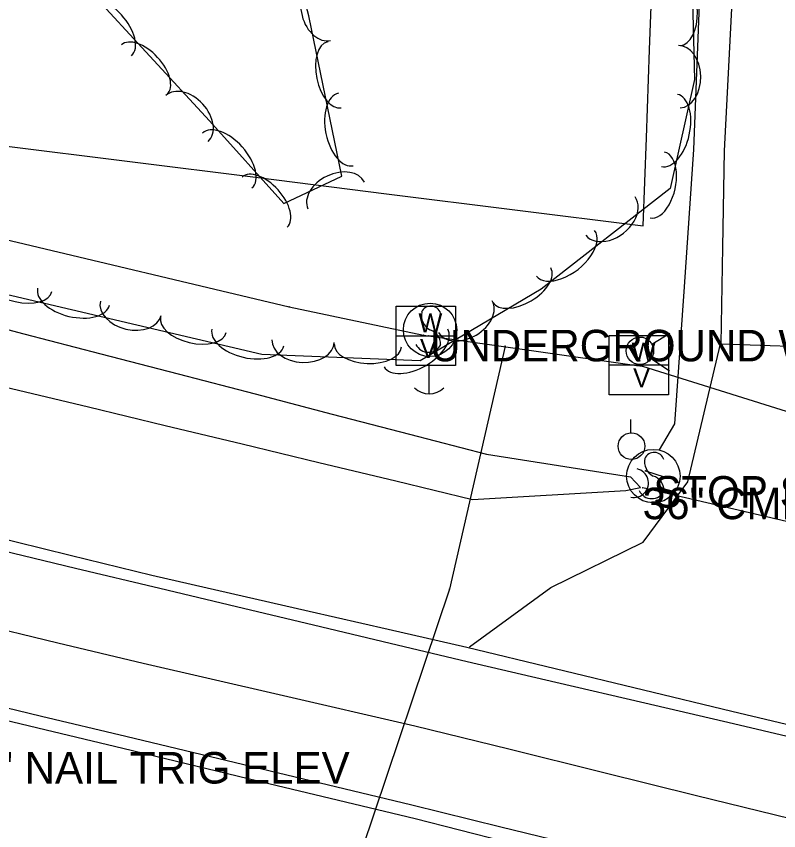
# Model space of a CAD drawing. Extents: x 1441650 to 1491889, y 345904 to 358319.
# Drawn here: x 1450968 to 1451089.1, y 353269.1 to 353398.4 of the extents above; entities that cross this region are included whole.
import ezdxf

# ---------------------------------------------------------------- set-up
doc = ezdxf.new("R2010")
doc.units = 0
for name, color, linetype in [('S_CROSS_DRAIN', 7, 'Continuous'), ('S_CROSS_DRAIN_ANNOT', 7, 'Continuous'), ('S_DITCHLINE', 7, 'Continuous'), ('S_DRG_PT_SYM', 7, 'Continuous'), ('S_EDGE_PAVEMENT', 7, 'Continuous'), ('S_GRAVEL_ROAD', 7, 'Continuous'), ('S_MSC_PT_SYM', 7, 'Continuous'), ('S_PAVEMENT_CROWN', 7, 'Continuous'), ('S_SECONDARY_CTL_ANNOT', 7, 'Continuous'), ('S_SHOULDER', 7, 'Continuous'), ('S_SIGN', 7, 'Continuous'), ('S_SIGN_ANNOT', 7, 'Continuous'), ('S_TREE', 7, 'Continuous'), ('S_UTILITY_POLE', 7, 'Continuous'), ('S_UTL_PT_SYM', 7, 'Continuous'), ('S_WATER_UTILITIES', 7, 'Continuous')]:
    doc.layers.add(name, color=color, linetype=linetype)

msp = doc.modelspace()

# ---------------------------------------------------------------- linework, layer by layer
at = {"layer": 'S_CROSS_DRAIN'}
msp.add_line((1451114.27, 353312.59), (1451067.5, 353323.6), dxfattribs=at)
msp.add_arc((1451066.12, 353324.34), 2.3, 257.1469, 77.4761, dxfattribs=at)
at = {"layer": 'S_DITCHLINE'}
for points in [[(1451081.51, 353583.7), (1451081.24, 353570.14), (1451080.98, 353556.59), (1451080.71, 353543.03), (1451080.44, 353529.48), (1451080.17, 353515.92), (1451079.9, 353502.36), (1451079.63, 353488.81), (1451079.36, 353475.25), (1451078.42, 353450.76), (1451077.48, 353426.27), (1451076.53, 353401.77), (1451075.59, 353377.28), (1451074.08, 353355.51), (1451072.56, 353333.74), (1451070.11, 353329.6)], [(1450831.65, 353381.19), (1450844.51, 353378.15), (1450857.04, 353375.18), (1450869.56, 353372.22), (1450882.09, 353369.25), (1450894.61, 353366.28), (1450907.13, 353363.32), (1450919.66, 353360.35), (1450932.18, 353357.39), (1450944.71, 353354.42), (1450956.95, 353351.23), (1450969.2, 353348.05), (1450981.44, 353344.86), (1450993.69, 353341.67), (1451005.94, 353338.48), (1451018.18, 353335.29), (1451030.43, 353332.11), (1451042.68, 353328.92), (1451065.54, 353325.34), (1451067.13, 353323.63)], [(1450829.49, 353373.88), (1450842.26, 353370.68), (1450854.83, 353367.5), (1450867.4, 353364.32), (1450879.97, 353361.13), (1450892.54, 353357.95), (1450905.12, 353354.77), (1450917.69, 353351.59), (1450930.26, 353348.41), (1450942.83, 353345.23), (1450955.04, 353342.29), (1450967.25, 353339.35), (1450979.45, 353336.42), (1450991.66, 353333.48), (1451003.87, 353330.54), (1451016.07, 353327.6), (1451028.28, 353324.67), (1451040.49, 353321.73), (1451064.83, 353323.16), (1451067.13, 353323.63)]]:
    msp.add_lwpolyline(points, dxfattribs=at)
at = {"layer": 'S_DRG_PT_SYM'}
msp.add_lwpolyline([(1451067.5, 353323.6), (1451067.5, 353323.65), (1451067.5, 353323.6), (1451067.45, 353323.6), (1451067.5, 353323.6), (1451067.5, 353323.55), (1451067.5, 353323.6), (1451067.55, 353323.6)], dxfattribs=at)
at = {"layer": 'S_EDGE_PAVEMENT'}
for points in [[(1450823.58, 353347.74), (1450835.74, 353344.83), (1450849.25, 353341.57), (1450862.76, 353338.32), (1450876.27, 353335.07), (1450889.78, 353331.81), (1450913.52, 353326.12), (1450937.25, 353320.43), (1450950.63, 353317.23), (1450964.01, 353314.03), (1450977.39, 353310.83), (1450990.77, 353307.63), (1451002.98, 353304.72), (1451015.18, 353301.82), (1451027.39, 353298.91), (1451039.6, 353296), (1451053.71, 353292.72), (1451067.83, 353289.43), (1451081.94, 353286.14), (1451096.06, 353282.85)], [(1451039.97, 353298.34), (1451052.91, 353307.73), (1451067.57, 353314.96), (1451074.68, 353324.55), (1451079.88, 353346.43), (1451092.44, 353346.01), (1451103.35, 353346.12), (1451106.46, 353341.59), (1451110.6, 353338.54), (1451119.58, 353334.06), (1451137.25, 353329.84), (1451154.93, 353325.61), (1451175.32, 353321.2), (1451195.71, 353316.78), (1451216.11, 353312.37), (1451236.5, 353307.96), (1451244, 353311.27), (1451247.51, 353313.37), (1451252.22, 353316.81), (1451258.38, 353327.82)], [(1450830.73, 353321.2), (1450843.9, 353318.04), (1450857.06, 353314.89), (1450870.22, 353311.74), (1450883.39, 353308.58), (1450907.63, 353302.76), (1450931.87, 353296.93), (1450945.25, 353293.73), (1450958.63, 353290.53), (1450972.01, 353287.34), (1450985.39, 353284.14), (1451008.11, 353278.7), (1451030.84, 353273.25), (1451044.97, 353269.78), (1451059.1, 353266.32), (1451073.24, 353262.85), (1451087.37, 353259.38), (1451099.74, 353256.51)]]:
    msp.add_lwpolyline(points, dxfattribs=at)
at = {"layer": 'S_GRAVEL_ROAD'}
msp.add_lwpolyline([(1451086.83, 353584.48), (1451086.85, 353571.29), (1451086.87, 353558.1), (1451086.9, 353544.9), (1451086.92, 353531.71), (1451086.46, 353517.63), (1451086, 353503.54), (1451085.54, 353489.45), (1451085.08, 353475.37), (1451084.52, 353462.63), (1451083.95, 353449.89), (1451083.39, 353437.15), (1451082.83, 353424.41), (1451081.65, 353400.75), (1451080.47, 353377.08), (1451080.19, 353361.77), (1451079.9, 353346.46)], dxfattribs=at)
at = {"layer": 'S_MSC_PT_SYM'}
for points in [[(1451067.93, 353326.26), (1451067.93, 353326.31), (1451067.93, 353326.26), (1451067.88, 353326.26), (1451067.93, 353326.26), (1451067.93, 353326.21), (1451067.93, 353326.26), (1451067.98, 353326.26)], [(1451070.92, 353325.33), (1451070.92, 353325.38), (1451070.92, 353325.33), (1451070.87, 353325.33), (1451070.92, 353325.33), (1451070.92, 353325.28), (1451070.92, 353325.33), (1451070.97, 353325.33)]]:
    msp.add_lwpolyline(points, dxfattribs=at)
at = {"layer": 'S_PAVEMENT_CROWN'}
msp.add_lwpolyline([(1450834.01, 353333.12), (1450847.14, 353329.9), (1450860.27, 353326.69), (1450873.4, 353323.47), (1450886.53, 353320.26), (1450910.25, 353314.51), (1450933.97, 353308.76), (1450947.51, 353305.5), (1450961.05, 353302.25), (1450974.59, 353298.99), (1450988.13, 353295.73), (1451009.73, 353290.77), (1451031.32, 353285.8), (1451046.23, 353282.12), (1451061.14, 353278.43), (1451076.05, 353274.74), (1451090.96, 353271.06)], dxfattribs=at)
at = {"layer": 'S_SHOULDER'}
for points in [[(1450824.18, 353349.95), (1450836.42, 353347.01), (1450849.81, 353343.71), (1450863.21, 353340.42), (1450876.6, 353337.12), (1450889.99, 353333.83), (1450913.88, 353328.09), (1450937.76, 353322.35), (1450950.7, 353319.2), (1450963.64, 353316.04), (1450976.57, 353312.89), (1450989.51, 353309.73), (1451002.02, 353306.87), (1451014.53, 353304.01), (1451027.04, 353301.15), (1451039.54, 353298.29), (1451053.58, 353294.91), (1451067.62, 353291.53), (1451081.66, 353288.14), (1451095.7, 353284.76)], [(1450830.29, 353319.65), (1450843.46, 353316.48), (1450856.63, 353313.3), (1450869.8, 353310.12), (1450882.97, 353306.94), (1450906.96, 353301.05), (1450930.95, 353295.16), (1450944.44, 353291.93), (1450957.93, 353288.7), (1450971.42, 353285.47), (1450984.91, 353282.23), (1451008.12, 353276.65), (1451031.33, 353271.07), (1451045.44, 353267.46), (1451059.55, 353263.84), (1451073.66, 353260.23), (1451087.76, 353256.62), (1451100.07, 353253.77)]]:
    msp.add_lwpolyline(points, dxfattribs=at)
at = {"layer": 'S_SIGN'}
msp.add_line((1451067.93, 353326.26), (1451070.92, 353325.33), dxfattribs=at)
for centre in [(1451033.72, 353348.66), (1451069.19, 353325.44)]:
    msp.add_circle(centre, 4.24, dxfattribs=at)
for centre, radius, start, end in [((1451034.89, 353350.92), 2.55, 167.1196, 241.9813), ((1451033.85, 353350.82), 1.62, 16.5258, 156.8957), ((1451033.02, 353346.38), 2.38, 358.6529, 73.7063), ((1451033.46, 353347.26), 2.17, 204.641, 335.359), ((1451070.35, 353327.69), 2.55, 167.1196, 241.9813), ((1451069.31, 353327.59), 1.62, 16.5258, 156.8957), ((1451068.49, 353323.16), 2.38, 358.6529, 73.7063), ((1451068.93, 353324.04), 2.17, 204.641, 335.359)]:
    msp.add_arc(centre, radius, start, end, dxfattribs=at)
at = {"layer": 'S_TREE'}
for points in [[(1450852.24, 353575.78), (1450857.17, 353552.77), (1450854.21, 353539.37), (1450848, 353528.9), (1450859.46, 353504.57), (1450890.34, 353466.47), (1450946.32, 353424.11), (1450979.75, 353402.41), (1450998.69, 353381.83), (1451010.51, 353368.7), (1451019.71, 353373.05), (1451014.45, 353398.5), (1451008.5, 353420.89), (1451025.86, 353434.13), (1451027.45, 353449.75), (1451001.4, 353446.33), (1450968.72, 353445.3), (1450934.63, 353475.8), (1450909.36, 353496.02), (1450896.01, 353516.09), (1450886.84, 353540.85), (1450882.03, 353567.8), (1450882.28, 353576.49)], [(1451081.45, 353507.22), (1451078.58, 353476.15), (1451074.5, 353436.69), (1451075.71, 353388.42), (1451071.87, 353371.08), (1451051.37, 353355.1), (1451032.15, 353343.74), (1451006.98, 353344.75), (1450902.46, 353369.26), (1450848.54, 353385.74), (1450833.65, 353392.55), (1450817.21, 353399.62), (1450798.23, 353391.97), (1450779.89, 353395.02), (1450763.79, 353414.42), (1450740.79, 353417.51), (1450719.03, 353412.74), (1450708.9, 353435.04), (1450659.3, 353448.63), (1450646.87, 353441.13), (1450629.34, 353447.78), (1450610.54, 353464.78)], [(1450822.89, 353395.73), (1450843.28, 353393.19), (1450863.67, 353390.64), (1450884.06, 353388.09), (1450904.46, 353385.55), (1450924.85, 353383), (1450945.24, 353380.46), (1450965.64, 353377.91), (1450986.03, 353375.37), (1451006.42, 353372.82), (1451026.81, 353370.27), (1451047.21, 353367.73), (1451067.6, 353365.18), (1451068.1, 353379.13), (1451068.6, 353393.09), (1451069.09, 353407.04)], [(1450822.89, 353395.73), (1450843.28, 353393.19), (1450863.67, 353390.64), (1450884.06, 353388.09), (1450904.46, 353385.55), (1450924.85, 353383), (1450945.24, 353380.46), (1450965.64, 353377.91), (1450986.03, 353375.37), (1451006.42, 353372.82), (1451026.81, 353370.27), (1451047.21, 353367.73), (1451067.6, 353365.18), (1451068.1, 353379.13), (1451068.6, 353393.09), (1451069.09, 353407.04)]]:
    msp.add_lwpolyline(points, dxfattribs=at)
for centre, major_axis, ratio, start_param, end_param in [((1451073.32, 353399.15), (-0.13, 5.34), 0.540699, 3.141593, 6.283185), ((1451016.66, 353399.41), (1.27, -4.79), 0.684317, 3.140814, 6.282406), ((1450982.32, 353396.49), (-3.97, 4.32), 0.54902, 3.141593, 6.283185), ((1450988.32, 353389.97), (-3.62, 3.93), 0.539658, 3.141593, 6.283185), ((1451018.54, 353389.15), (1.08, -5.24), 0.539932, 3.141593, 6.283185), ((1451073.32, 353388.85), (-0.12, 4.95), 0.68531, 3.141593, 6.283185), ((1450995.11, 353382.21), (-3.36, 3.65), 0.68399, 3.141593, 6.283185), ((1451020.34, 353380.46), (1.19, -5.75), 0.549299, 3.141593, 6.283185), ((1451071.75, 353380.32), (1.27, 5.73), 0.550084, 3.141602, 6.283194), ((1451001.5, 353375.54), (-3.93, 4.36), 0.54902, 3.141593, 6.283185), ((1451069.83, 353371.66), (1.16, 5.22), 0.540704, 3.141601, 6.283194), ((1451007.43, 353368.95), (-3.58, 3.97), 0.539658, 3.141593, 6.283185), ((1451018.81, 353369.99), (-4.48, -2.12), 0.685194, 3.141593, 6.283185), ((1451062.38, 353366.71), (3.91, 3.04), 0.685511, 3.141741, 6.283334), ((1451055.24, 353360.81), (4.63, 3.61), 0.550241, 3.141683, 6.283276), ((1451048.31, 353355.76), (4.6, 2.72), 0.540693, 3.141593, 6.283185), ((1450968.45, 353355.96), (5.21, -1.22), 0.540694, 3.141593, 6.283185), ((1450977.09, 353353.94), (5.71, -1.34), 0.550074, 3.141593, 6.283185), ((1450986.16, 353352.08), (4.82, -1.13), 0.685304, 3.141593, 6.283185), ((1451039.31, 353350.74), (4.27, 2.52), 0.685303, 3.141593, 6.283185), ((1450996.13, 353349.47), (5.21, -1.22), 0.540694, 3.141593, 6.283185), ((1451004.77, 353347.45), (5.71, -1.34), 0.550074, 3.141593, 6.283185), ((1451031.47, 353345.8), (5.05, 2.99), 0.550073, 3.141593, 6.283185), ((1451013.56, 353346.87), (4.95, -0.2), 0.685303, 3.141593, 6.283185), ((1451023.84, 353346.2), (5.34, -0.22), 0.540693, 3.141593, 6.283185)]:
    msp.add_ellipse(centre, major_axis=major_axis, ratio=ratio, start_param=start_param, end_param=end_param, dxfattribs=at)
at = {"layer": 'S_UTILITY_POLE'}
for p, q in [((1451033.51, 353343.22), (1451033.51, 353338.49)), ((1451065.6, 353332.33), (1451065.6, 353334.44))]:
    msp.add_line(p, q, dxfattribs=at)
msp.add_circle((1451065.72, 353330.19), 2.13, dxfattribs=at)
msp.add_arc((1451033.58, 353341.92), 3.41, 226.3972, 313.6028, dxfattribs=at)
at = {"layer": 'S_UTL_PT_SYM'}
for points in [[(1451011.33, 353352.33), (1451011.33, 353352.38), (1451011.33, 353352.33), (1451011.28, 353352.33), (1451011.33, 353352.33), (1451011.33, 353352.28), (1451011.33, 353352.33), (1451011.38, 353352.33)], [(1451032.7, 353347.84), (1451032.7, 353347.89), (1451032.7, 353347.84), (1451032.65, 353347.84), (1451032.7, 353347.84), (1451032.7, 353347.79), (1451032.7, 353347.84), (1451032.75, 353347.84)], [(1451033.46, 353347.72), (1451033.46, 353347.77), (1451033.46, 353347.72), (1451033.41, 353347.72), (1451033.46, 353347.72), (1451033.46, 353347.67), (1451033.46, 353347.72), (1451033.51, 353347.72)], [(1451045.63, 353346.05), (1451045.63, 353346.1), (1451045.63, 353346.05), (1451045.58, 353346.05), (1451045.63, 353346.05), (1451045.63, 353346), (1451045.63, 353346.05), (1451045.68, 353346.05)], [(1451066.59, 353343), (1451066.59, 353343.05), (1451066.59, 353343), (1451066.54, 353343), (1451066.59, 353343), (1451066.59, 353342.95), (1451066.59, 353343), (1451066.64, 353343)], [(1451067.46, 353342.9), (1451067.46, 353342.95), (1451067.46, 353342.9), (1451067.41, 353342.9), (1451067.46, 353342.9), (1451067.46, 353342.85), (1451067.46, 353342.9), (1451067.51, 353342.9)], [(1451036.81, 353307.47), (1451036.81, 353307.52), (1451036.81, 353307.47), (1451036.76, 353307.47), (1451036.81, 353307.47), (1451036.81, 353307.42), (1451036.81, 353307.47), (1451036.86, 353307.47)]]:
    msp.add_lwpolyline(points, dxfattribs=at)
at = {"layer": 'S_WATER_UTILITIES'}
for p, q in [((1450477.52, 353478.74), (1451011.33, 353352.33)), ((1451011.33, 353352.33), (1451032.7, 353347.84)), ((1451028.33, 353352.42), (1451037.75, 353352.42)), ((1451028.33, 353343), (1451028.33, 353352.42)), ((1451037.75, 353352.42), (1451037.75, 353343)), ((1451028.33, 353347.73), (1451037.75, 353347.73)), ((1451032.7, 353347.84), (1451033.46, 353347.72)), ((1451033.46, 353347.72), (1451066.59, 353343)), ((1451062.2, 353347.76), (1451071.62, 353347.76)), ((1451062.2, 353338.35), (1451062.2, 353347.76)), ((1451068.97, 353346.4), (1451071.79, 353348.13)), ((1451071.62, 353347.76), (1451071.62, 353338.35)), ((1451045.63, 353346.05), (1451036.81, 353307.47)), ((1451068.84, 353344.09), (1451071.75, 353342.16)), ((1451037.75, 353343), (1451028.33, 353343)), ((1451062.2, 353343.08), (1451071.62, 353343.08)), ((1451066.59, 353343), (1451067.46, 353342.9)), ((1451067.46, 353342.9), (1451114.78, 353328.08)), ((1451071.62, 353338.35), (1451062.2, 353338.35)), ((1451036.81, 353307.47), (1451022.13, 353263.89))]:
    msp.add_line(p, q, dxfattribs=at)
msp.add_circle((1451067.06, 353345.34), 2.18, dxfattribs=at)

# ---------------------------------------------------------------- texts
at = {"layer": 'S_CROSS_DRAIN_ANNOT'}
msp.add_text('36" CMP WITH 50% FILL', height=5, dxfattribs=at).set_placement((1451067.5, 353318.6))
at = {"layer": 'S_SECONDARY_CTL_ANNOT'}
msp.add_text('PD:SET 8" NAIL TRIG ELEV', height=5, dxfattribs=at).set_placement((1450935.35, 353276.63))
at = {"layer": 'S_SIGN_ANNOT'}
for s, p in [('UNDERGROUND WATERLINE', (1451033.72, 353343.66)), ('STOP SIGN HUMES ROAD SIGN', (1451069.19, 353320.44))]:
    msp.add_text(s, height=5, dxfattribs=at).set_placement(p)
at = {"layer": 'S_WATER_UTILITIES'}
for s, p in [('W', (1451031.88, 353348.26)), ('V', (1451032.12, 353344.2)), ('W', (1451065.75, 353343.61)), ('V', (1451065.99, 353339.54))]:
    msp.add_text(s, height=3, rotation=360, dxfattribs=at).set_placement(p)

doc.saveas('drawing.dxf')
